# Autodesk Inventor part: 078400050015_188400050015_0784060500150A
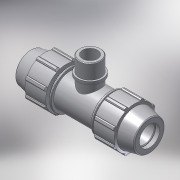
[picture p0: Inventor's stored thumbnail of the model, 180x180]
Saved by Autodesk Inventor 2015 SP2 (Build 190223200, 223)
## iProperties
Created: 2017-02
Part Number: 078400050015_188400050015_0784060500150A
Material: PVC-Piping
Description: PLASSON TEE WITH THREADED MALE OFFTAKE 50-1.1/2"-50
Document SubType Name: Modeling
Designer: KIM
Mass: 92.6774 g
Surface Area: 199.44 cm^2
Volume: 66.1981 cm^3
Density: 1.4 g/cm^3
Appearance: Smooth - White
Author: Кирилл
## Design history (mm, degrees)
derived "07840.ipt"
feature "Solid1::07840.ipt"
feature "Solid2::07840.ipt"
tag "TaggingFeature1"
body "Solid1"
body "Solid2"
other parameters: "d4" = 9.58333, "d5" = 27.6, "d7" = 96, "d11" = 3.83333, "d13" = 120 deg, "d14" = 75, "d15" = 12 deg, "d16" = 83.52, "d18" = 2.5, "d19" = 35 deg, "d20" = 17.5 deg, "d21" = 89.28, "d23" = 0, "d25" = 360 deg, "d27" = 1.92, "d33" = 1, "d42" = 41.4, "d43" = 2.88, "d46" = 1.5, "d68" = 3.83333, "d72" = 77, "d73" = 47.803, "d74" = 22, "d75" = 54.97345, "d76" = 33.4621, "d77" = 26.4, "d80" = 1.43409, "d91" = 72, "d93" = 93, "d95" = 45, "d101" = 0, "d103" = 0, "d105" = 0, "E_" = 96, "A_" = 77, "l_" = 93, "l_2" = 22, "R_" = 47.803
